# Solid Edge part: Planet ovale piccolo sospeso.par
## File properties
Title: Planet ovale piccolo sospeso
Author: DESYS
Template: Iso Part.par
Last saved by: s.pallini
Revision: 14
Application: Solid Edge
Accuracy: 0,990
Tipo di contenuto documento: 0
Document Number: 8110
Revision: 0
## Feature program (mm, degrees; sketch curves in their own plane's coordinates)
lofted protrusion "unnamed LoftedProtrusion 1"
lofted cutout "unnamed LoftedCutout 1"
sketch for "unnamed Protrusion 1" plane through (0, 160, 0) normal (0, 1, 0) x-axis (1, 0, 0)
  arc centre (0, 0) radius 160 from (160, 0) to (160, 0) cw
extrude "unnamed Protrusion 1" add finite 7 along +normal
sketch for "ScavoEstrusione_1" #1 plane through (0, 167, 0) normal (0, 1, 0) x-axis (1, 0, 0)
  arc centre (0, 0) radius 120 from (120, 0) to (120, 0)
sketch for "ScavoEstrusione_1" #2 plane through (0, 167, 0) normal (0, 1, 0) x-axis (1, 0, 0)
  circle centre (0, 0) radius 35
extrude "ScavoEstrusione_1" cut finite 50 along -normal
sketch for "Foro_1" plane through (0, 167, 0) normal (0, 1, 0) x-axis (1, 0, 0)
  hole centre (0, 0) bore radius 25
hole "Foro_1" diameter 50 through
fillet "Rotondo_2" radius 15
fillet "Rotondo_3" radius 10
fillet "Rotondo_4" radius 5
fillet "Rotondo_5" radius 15
sketch for "ProtrusioneEstrusa_2" plane through (0, 0, 0) normal (1, 0, 0) x-axis (0, 1, 0)
extrude "ProtrusioneEstrusa_2" add finite 230 symmetric
sketch for "ScavoEstrusione_2" plane through (0, 0, 0) normal (1, 0, 0) x-axis (0, 1, 0)
extrude "ScavoEstrusione_2" cut finite 180 symmetric
sketch for "Foro_2" plane through (0, 0, 44.9962) normal (0, -1, 0) x-axis (-1, 0, 0)
hole "Foro_2" diameter 35 through
sketch for "unnamed Cutout 1" plane through (0, 83.5, 280) normal (0, 0, 1) x-axis (-1, 0, 0)
extrude "unnamed Cutout 1" cut through along -normal
sketch for "unnamed Protrusion 2" plane through (0, 0, 0) normal (1, 0, 0) x-axis (0, 1, 0)
extrude "unnamed Protrusion 2" add to key point symmetric
fillet "Rotondo_7" radius 5
fillet "Rotondo_8" radius 30
fillet "Rotondo_9" radius 10
fillet "Rotondo_10" radius 10
fillet "Rotondo_11" radius 5
fillet "Rotondo_12" radius 5
sketch for "ScavoEstrusione_4" plane through (0, 0, 0) normal (0, 0, 1) x-axis (1, 0, 0)
  circle centre (0, 25) radius 10
extrude "ScavoEstrusione_4" cut finite 165 along +normal
fillet "Rotondo_18" radius 20
fillet "Rotondo_19" radius 10
sketch for "unnamed Cutout 2" #1 plane through (0, 86, 280) normal (0, 0, 1) x-axis (-1, 0, 0)
sketch for "unnamed Cutout 2" #2 plane through (0, 86, 280) normal (0, 0, 1) x-axis (-1, 0, 0)
extrude "unnamed Cutout 2" cut through along -normal
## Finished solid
Body 1: solid body, 97 faces, 227 edges, 131 vertices.
  Faces by surface: cylinder 32, plane 23, blend 20, torus 13, sphere 6, spline 2, swept 1
  Edges by curve: circle 74, intersection 74, line 71, ellipse 8
Bounding box of the edges (mm; curved faces can reach further): 479.445 x 167.000 x 470.659, from (-239.7222, 0, -190.6593) to (239.7224, 167, 280).
Cylindrical faces by radius (mm): R5 x14, R10 x11, R17.5 x1, R25 x1, R35 x1, R55 x1, R148.0234 x2, R175.5633 x1
Toroidal faces (ring radius, tube radius in mm): R5 r5 x2, R22.5 r5 x1, R30 r5 x1, R45 r10 x1, R60 r5 x2, R153.0234 r5 x4, R165.5633 r10 x2
Spherical faces by radius (mm): R5 x4, R10 x2
Planar faces by outward normal: +x 3, +y 7, +z 3, -x 3, -y 3, -z 4
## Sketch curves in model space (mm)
arc centre (0, -49.8604, -18.5294) radius 150 from (0, 100, -25) through (0, 70.6732, -107.8135) to (0, 0, -160)
arc centre (0, -49.8604, 18.5294) radius 150 from (0, 100, 25) through (0, 70.6732, 107.8135) to (0, 0, 160)
arc centre (36.6009, -99.6633, 0) radius 200 from (25, 100, 0) through (131.7043, 76.278, 0) to (210, 0, 0)
arc centre (-36.6009, -99.6633, 0) radius 200 from (-25, 100, 0) through (-131.7043, 76.278, 0) to (-210, 0, 0)
circle centre (0, 100, 0) radius 25
ellipse centre (0, 0, 0) radii 210, 160
arc centre (0, 15.7496, -30.777) radius 160 from (0, 0, -190) through (0, 98.2149, -167.8882) to (0, 160, -100)
arc centre (0, 15.7496, 30.777) radius 160 from (0, 0, 190) through (0, 98.2149, 167.8882) to (0, 160, 100)
arc centre (40, 0, 0) radius 200 from (160, 160, 0) through (218.8854, 89.4427, 0) to (240, 0, 0)
arc centre (-40, 0, 0) radius 200 from (-160, 160, 0) through (-218.8854, 89.4427, 0) to (-240, 0, 0)
ellipse centre (0, 160, 0) radii 160, 100
ellipse centre (0, 0, 0) radii 240, 190
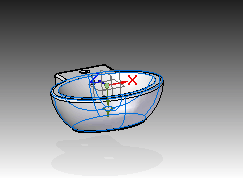
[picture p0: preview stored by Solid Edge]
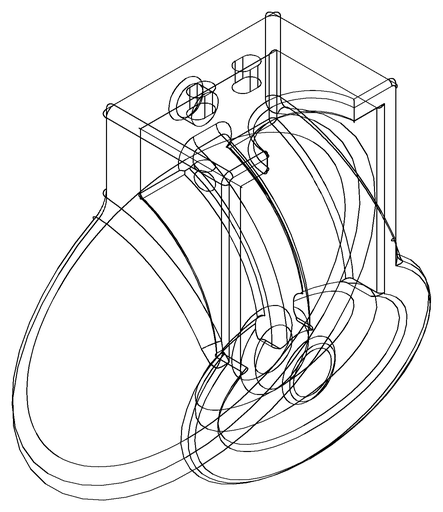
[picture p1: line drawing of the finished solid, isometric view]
